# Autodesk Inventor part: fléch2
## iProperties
Shininess: 64.0
Length Units: 11269
Angle Units: 11279
Time Units: 11290
Mass Units: 11283
Length Display Precision: 3
Angle Display Precision: 2
Compacted: True
Part Number: fléch2
Document SubType Name: Modeling
Created: 2003-10
Material: Par défaut
Designer: Maison
Density: 0.0
Volumn: 0.0
Area: 0.0
PropertySet Name: Model Information
Control State: 0
Master: False
Checked Out: False
Author: Maison
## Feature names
1. Extrusion1
